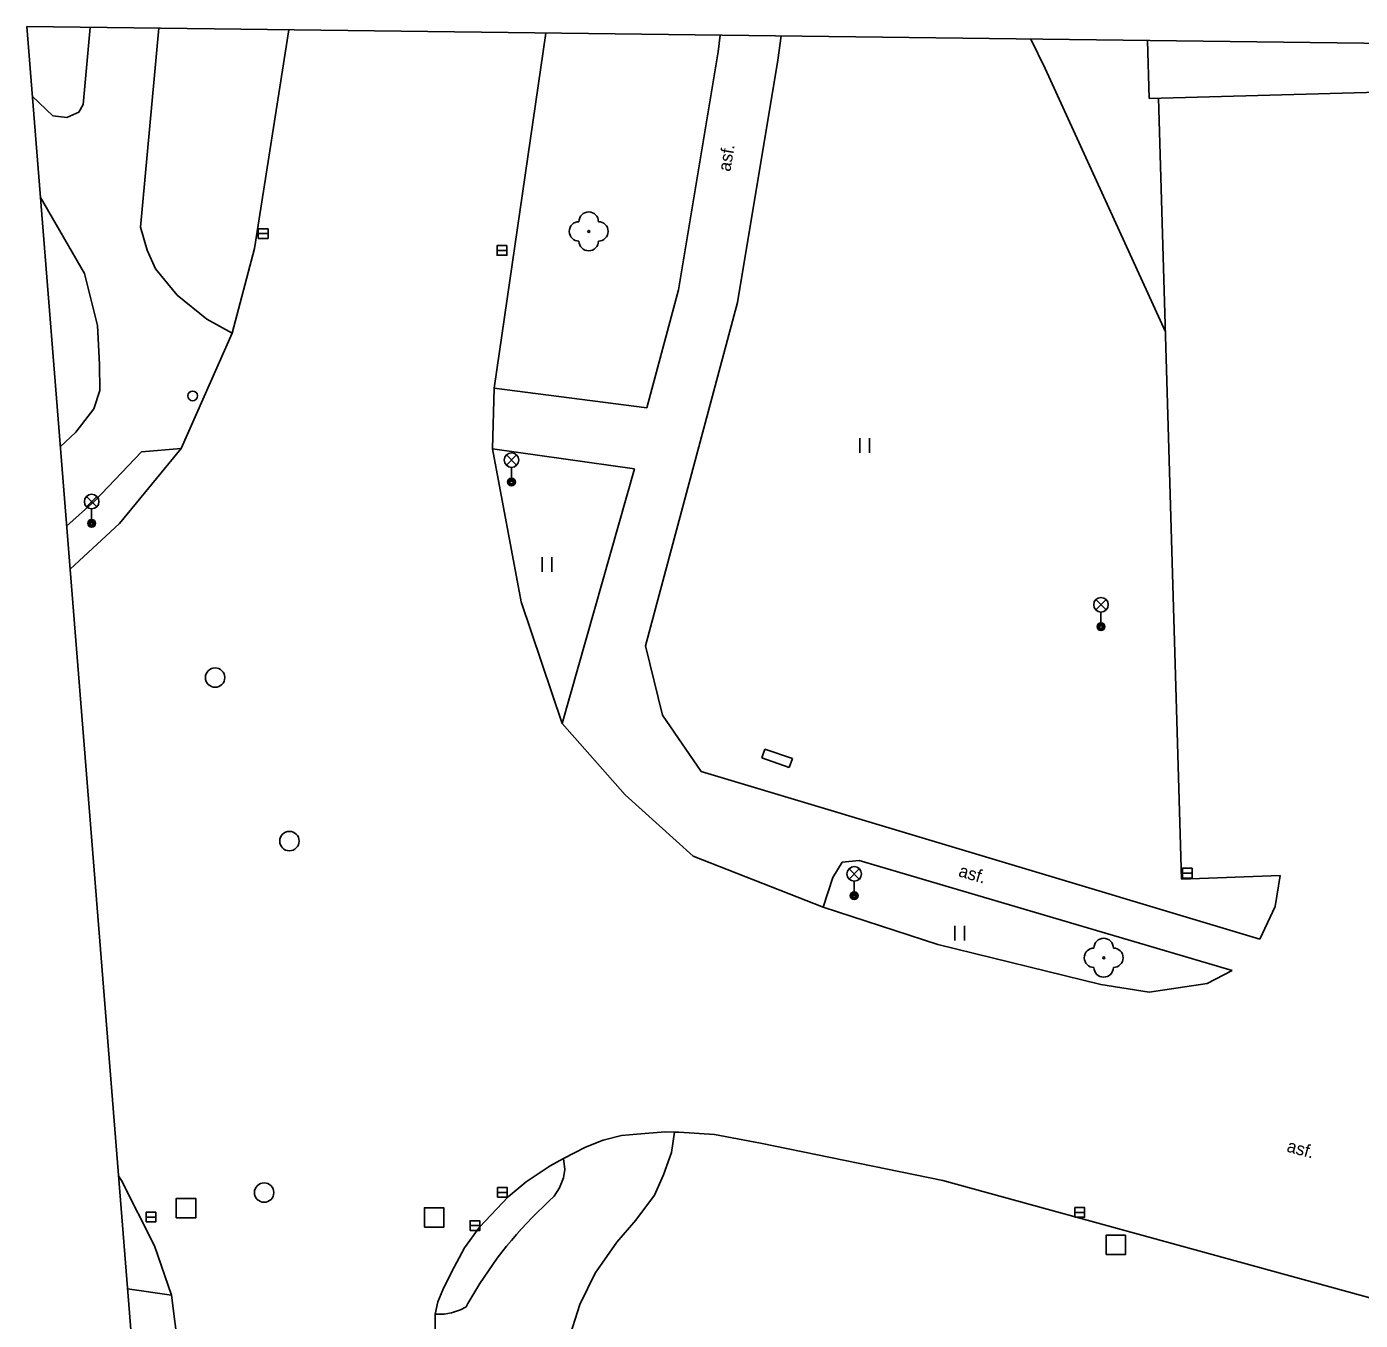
# Model space of a CAD drawing. Extents: x -641829 to -641525, y -1114855 to -1114359.
# Drawn here: x -641828.7 to -641760.1, y -1114425.4 to -1114358.9 of the extents above; entities that cross this region are included whole.
import ezdxf

# ---------------------------------------------------------------- set-up
doc = ezdxf.new("R2010")
doc.units = 0
for name, color, linetype in [('Vrstva 1', 7, 'Continuous'), ('Vrstva 10', 7, 'Continuous'), ('Vrstva 11', 7, 'Continuous'), ('Vrstva 14', 7, 'Continuous'), ('Vrstva 22', 7, 'Continuous'), ('Vrstva 26', 7, 'Continuous'), ('Vrstva 27', 7, 'Continuous'), ('Vrstva 28', 7, 'Continuous'), ('Vrstva 33', 7, 'Continuous'), ('Vrstva 36', 7, 'Continuous'), ('Vrstva 40', 7, 'Continuous'), ('Vrstva 5', 7, 'Continuous')]:
    doc.layers.add(name, color=color, linetype=linetype)

msp = doc.modelspace()

# ---------------------------------------------------------------- linework, layer by layer
at = {"layer": 'Vrstva 1'}
for p, q in [((-641525.3, -1114362.64), (-641828.67, -1114358.89)), ((-641828.67, -1114358.89), (-641812.64, -1114559.36))]:
    msp.add_line(p, q, dxfattribs=at)
at = {"layer": 'Vrstva 10'}
for p, q in [((-641815.193, -1114359.057), (-641816.95, -1114370.3)), ((-641801.975, -1114359.22), (-641804.63, -1114377.48)), ((-641769.29, -1114402.74), (-641770.48, -1114362.57)), ((-641816.95, -1114370.3), (-641818.1, -1114374.66)), ((-641818.1, -1114374.66), (-641820.73, -1114380.59)), ((-641804.63, -1114377.48), (-641804.72, -1114380.61)), ((-641820.73, -1114380.59), (-641823.9, -1114384.44)), ((-641804.72, -1114380.61), (-641803.25, -1114388.47)), ((-641823.9, -1114384.44), (-641826.439, -1114386.788)), ((-641803.25, -1114388.47), (-641801.13, -1114394.74)), ((-641801.13, -1114394.74), (-641797.9, -1114398.4)), ((-641797.9, -1114398.4), (-641794.4, -1114401.56)), ((-641787.71, -1114404.18), (-641794.4, -1114401.56)), ((-641764.22, -1114402.55), (-641769.29, -1114402.74)), ((-641764.47, -1114404.14), (-641764.22, -1114402.55)), ((-641787.71, -1114404.18), (-641781.82, -1114406.1)), ((-641765.26, -1114405.83), (-641764.47, -1114404.14)), ((-641781.82, -1114406.1), (-641773.44, -1114408.15)), ((-641767.97, -1114408.11), (-641766.69, -1114407.44)), ((-641773.44, -1114408.15), (-641770.95, -1114408.55)), ((-641770.95, -1114408.55), (-641767.97, -1114408.11)), ((-641799.02, -1114416.16), (-641798.08, -1114415.93)), ((-641798.08, -1114415.93), (-641797.3, -1114415.85)), ((-641797.3, -1114415.85), (-641795.84, -1114415.74)), ((-641795.84, -1114415.74), (-641795.36, -1114415.75)), ((-641795.36, -1114415.75), (-641795.13, -1114415.75)), ((-641793.31, -1114415.87), (-641795.13, -1114415.75)), ((-641790.93, -1114416.31), (-641793.31, -1114415.87)), ((-641801.06, -1114417.11), (-641799.93, -1114416.53)), ((-641799.93, -1114416.53), (-641799.02, -1114416.16)), ((-641790.93, -1114416.31), (-641781.57, -1114418.24)), ((-641801.75, -1114417.48), (-641801.06, -1114417.11)), ((-641823.943, -1114418.005), (-641823.8, -1114418.23)), ((-641802.99, -1114418.31), (-641801.75, -1114417.48)), ((-641823.8, -1114418.23), (-641822.1, -1114421.59)), ((-641803.91, -1114419.07), (-641802.99, -1114418.31)), ((-641781.57, -1114418.24), (-641753.07, -1114426.08)), ((-641805.38, -1114420.63), (-641803.91, -1114419.07)), ((-641806.16, -1114421.7), (-641805.38, -1114420.63)), ((-641822.1, -1114421.59), (-641821.23, -1114424.14)), ((-641806.82, -1114422.96), (-641806.16, -1114421.7)), ((-641807.27, -1114423.86), (-641806.82, -1114422.96)), ((-641821.23, -1114424.14), (-641820.82, -1114427.32)), ((-641807.27, -1114423.86), (-641807.52, -1114424.48)), ((-641807.52, -1114424.48), (-641807.67, -1114425.11)), ((-641807.68, -1114427.59), (-641807.67, -1114425.11))]:
    msp.add_line(p, q, dxfattribs=at)
at = {"layer": 'Vrstva 11'}
for p, q in [((-641825.77, -1114362.9), (-641825.406, -1114358.93)), ((-641822.82, -1114369.21), (-641821.866, -1114358.974)), ((-641793.11, -1114360.18), (-641793.003, -1114359.331)), ((-641790.04, -1114360.62), (-641789.882, -1114359.369)), ((-641795.15, -1114372.42), (-641793.11, -1114360.18)), ((-641792.12, -1114373.08), (-641790.04, -1114360.62)), ((-641828.384, -1114362.462), (-641827.32, -1114363.47)), ((-641825.77, -1114362.9), (-641825.99, -1114363.28)), ((-641826.61, -1114363.57), (-641827.32, -1114363.47)), ((-641825.99, -1114363.28), (-641826.61, -1114363.57)), ((-641827.97, -1114367.644), (-641825.69, -1114371.58)), ((-641822.48, -1114370.39), (-641822.82, -1114369.21)), ((-641822.05, -1114371.35), (-641822.48, -1114370.39)), ((-641820.94, -1114372.7), (-641822.05, -1114371.35)), ((-641825.02, -1114374.26), (-641825.69, -1114371.58)), ((-641819.4, -1114373.93), (-641820.94, -1114372.7)), ((-641796.78, -1114378.49), (-641795.15, -1114372.42)), ((-641796.85, -1114390.73), (-641792.12, -1114373.08)), ((-641818.1, -1114374.66), (-641819.4, -1114373.93)), ((-641824.92, -1114376.26), (-641825.02, -1114374.26)), ((-641824.9, -1114377.61), (-641824.92, -1114376.26)), ((-641796.78, -1114378.49), (-641804.63, -1114377.48)), ((-641825.21, -1114378.55), (-641824.9, -1114377.61)), ((-641825.21, -1114378.55), (-641826.15, -1114379.75)), ((-641826.15, -1114379.75), (-641826.942, -1114380.503)), ((-641822.76, -1114380.75), (-641825.16, -1114383.28)), ((-641822.76, -1114380.75), (-641820.73, -1114380.59)), ((-641797.42, -1114381.63), (-641804.72, -1114380.61)), ((-641801.13, -1114394.74), (-641797.42, -1114381.63)), ((-641825.16, -1114383.28), (-641826.616, -1114384.574)), ((-641795.98, -1114394.3), (-641796.85, -1114390.73)), ((-641793.99, -1114397.2), (-641795.98, -1114394.3)), ((-641790.71, -1114396.05), (-641790.87, -1114396.49)), ((-641789.3, -1114396.54), (-641790.71, -1114396.05)), ((-641790.87, -1114396.49), (-641789.46, -1114397)), ((-641789.3, -1114396.54), (-641789.46, -1114397)), ((-641765.26, -1114405.83), (-641793.99, -1114397.2)), ((-641786.73, -1114401.86), (-641787.22, -1114402.65)), ((-641785.86, -1114401.77), (-641786.73, -1114401.86)), ((-641766.69, -1114407.44), (-641785.86, -1114401.77)), ((-641787.71, -1114404.18), (-641787.22, -1114402.65)), ((-641795.36, -1114415.75), (-641795.52, -1114416.8)), ((-641801, -1114417.67), (-641801.06, -1114417.11)), ((-641795.52, -1114416.8), (-641795.93, -1114417.95)), ((-641801.07, -1114418.1), (-641801, -1114417.67)), ((-641795.93, -1114417.95), (-641796.38, -1114418.99)), ((-641801.54, -1114419.05), (-641801.27, -1114418.62)), ((-641801.27, -1114418.62), (-641801.07, -1114418.1)), ((-641802.12, -1114419.59), (-641801.83, -1114419.32)), ((-641801.83, -1114419.32), (-641801.54, -1114419.05)), ((-641796.38, -1114418.99), (-641797.34, -1114420.28)), ((-641802.68, -1114420.14), (-641802.4, -1114419.86)), ((-641802.4, -1114419.86), (-641802.12, -1114419.59)), ((-641803.48, -1114421.01), (-641803.22, -1114420.72)), ((-641803.22, -1114420.72), (-641802.95, -1114420.43)), ((-641802.95, -1114420.43), (-641802.68, -1114420.14)), ((-641797.34, -1114420.28), (-641798.32, -1114421.41)), ((-641803.99, -1114421.62), (-641803.74, -1114421.32)), ((-641803.74, -1114421.32), (-641803.48, -1114421.01)), ((-641798.32, -1114421.41), (-641799.44, -1114423)), ((-641804.47, -1114422.24), (-641804.23, -1114421.93)), ((-641804.23, -1114421.93), (-641803.99, -1114421.62)), ((-641804.93, -1114422.89), (-641804.7, -1114422.56)), ((-641804.7, -1114422.56), (-641804.47, -1114422.24)), ((-641805.58, -1114423.88), (-641805.37, -1114423.54)), ((-641805.37, -1114423.54), (-641805.15, -1114423.21)), ((-641805.15, -1114423.21), (-641804.93, -1114422.89)), ((-641799.44, -1114423), (-641800.22, -1114424.61)), ((-641823.478, -1114423.816), (-641821.23, -1114424.14)), ((-641805.98, -1114424.56), (-641805.78, -1114424.22)), ((-641805.78, -1114424.22), (-641805.58, -1114423.88)), ((-641806.36, -1114424.89), (-641806.82, -1114425.04)), ((-641806.07, -1114424.73), (-641806.36, -1114424.89)), ((-641806.07, -1114424.73), (-641805.98, -1114424.56)), ((-641800.22, -1114424.61), (-641800.95, -1114426.88)), ((-641807.2, -1114425.11), (-641807.67, -1114425.11)), ((-641806.82, -1114425.04), (-641807.2, -1114425.11))]:
    msp.add_line(p, q, dxfattribs=at)
at = {"layer": 'Vrstva 14'}
for p, q in [((-641777.038, -1114359.528), (-641776.3, -1114361.05)), ((-641776.3, -1114361.05), (-641770.12, -1114374.59))]:
    msp.add_line(p, q, dxfattribs=at)
at = {"layer": 'Vrstva 22'}
for centre in [(-641799.77, -1114369.42), (-641773.29, -1114406.78)]:
    msp.add_circle(centre, 0.05, dxfattribs=at)
for centre, start, end in [((-641799.77, -1114368.92), 0, 180), ((-641800.27, -1114369.42), 90, 270), ((-641799.27, -1114369.42), 270, 90), ((-641799.77, -1114369.92), 180, 0), ((-641773.79, -1114406.78), 90, 270), ((-641773.29, -1114406.28), 0, 180), ((-641772.79, -1114406.78), 270, 90), ((-641773.29, -1114407.28), 180, 0)]:
    msp.add_arc(centre, 0.5, start, end, dxfattribs=at)
at = {"layer": 'Vrstva 26'}
for points in [[(-641820.98, -1114420.16), (-641819.98, -1114420.16), (-641819.98, -1114419.16), (-641820.98, -1114419.16)], [(-641808.22, -1114420.64), (-641807.22, -1114420.64), (-641807.22, -1114419.64), (-641808.22, -1114419.64)], [(-641773.17, -1114422.05), (-641772.17, -1114422.05), (-641772.17, -1114421.05), (-641773.17, -1114421.05)]]:
    msp.add_lwpolyline(points, close=True, dxfattribs=at)
at = {"layer": 'Vrstva 27'}
for p, q in [((-641816.26, -1114369.53), (-641816.76, -1114369.53)), ((-641803.98, -1114370.4), (-641804.48, -1114370.4)), ((-641768.74, -1114402.43), (-641769.24, -1114402.43)), ((-641804.46, -1114418.85), (-641803.96, -1114418.85)), ((-641774.77, -1114419.88), (-641774.27, -1114419.88)), ((-641822.53, -1114420.12), (-641822.03, -1114420.12)), ((-641805.87, -1114420.56), (-641805.37, -1114420.56))]:
    msp.add_line(p, q, dxfattribs=at)
for points in [[(-641816.26, -1114369.28), (-641816.76, -1114369.28), (-641816.76, -1114369.78), (-641816.26, -1114369.78)], [(-641803.98, -1114370.15), (-641804.48, -1114370.15), (-641804.48, -1114370.65), (-641803.98, -1114370.65)], [(-641768.74, -1114402.18), (-641769.24, -1114402.18), (-641769.24, -1114402.68), (-641768.74, -1114402.68)], [(-641804.46, -1114419.1), (-641803.96, -1114419.1), (-641803.96, -1114418.6), (-641804.46, -1114418.6)], [(-641822.53, -1114420.37), (-641822.03, -1114420.37), (-641822.03, -1114419.87), (-641822.53, -1114419.87)], [(-641774.77, -1114420.13), (-641774.27, -1114420.13), (-641774.27, -1114419.63), (-641774.77, -1114419.63)], [(-641805.87, -1114420.81), (-641805.37, -1114420.81), (-641805.37, -1114420.31), (-641805.87, -1114420.31)]]:
    msp.add_lwpolyline(points, close=True, dxfattribs=at)
for centre in [(-641818.98, -1114392.37), (-641815.16, -1114400.78), (-641816.46, -1114418.86)]:
    msp.add_circle(centre, 0.5, dxfattribs=at)
at = {"layer": 'Vrstva 28'}
msp.add_circle((-641820.13, -1114377.88), 0.25, dxfattribs=at)
at = {"layer": 'Vrstva 33'}
for p, q in [((-641804.004, -1114381.45), (-641803.476, -1114380.92)), ((-641804.004, -1114380.92), (-641803.476, -1114381.45)), ((-641803.74, -1114381.56), (-641803.74, -1114382.31)), ((-641825.594, -1114383.58), (-641825.066, -1114383.05)), ((-641825.594, -1114383.05), (-641825.066, -1114383.58)), ((-641825.33, -1114383.69), (-641825.33, -1114384.44)), ((-641773.694, -1114388.89), (-641773.166, -1114388.36)), ((-641773.694, -1114388.36), (-641773.166, -1114388.89)), ((-641773.43, -1114389), (-641773.43, -1114389.75)), ((-641786.384, -1114402.73), (-641785.856, -1114402.2)), ((-641786.384, -1114402.2), (-641785.856, -1114402.73)), ((-641786.12, -1114402.84), (-641786.12, -1114403.59))]:
    msp.add_line(p, q, dxfattribs=at)
for centre, radius in [((-641803.74, -1114381.185), 0.375), ((-641803.74, -1114382.31), 0.2), ((-641803.74, -1114382.31), 0.145), ((-641803.74, -1114382.31), 0.0876), ((-641825.33, -1114383.315), 0.375), ((-641825.33, -1114384.44), 0.2), ((-641825.33, -1114384.44), 0.145), ((-641825.33, -1114384.44), 0.0876), ((-641773.43, -1114388.625), 0.375), ((-641773.43, -1114389.75), 0.2), ((-641773.43, -1114389.75), 0.145), ((-641773.43, -1114389.75), 0.0876), ((-641786.12, -1114402.465), 0.375), ((-641786.12, -1114403.59), 0.2), ((-641786.12, -1114403.59), 0.145), ((-641786.12, -1114403.59), 0.0876)]:
    msp.add_circle(centre, radius, dxfattribs=at)
at = {"layer": 'Vrstva 36'}
for p, q in [((-641785.834, -1114380.812), (-641785.834, -1114380.064)), ((-641785.334, -1114380.812), (-641785.334, -1114380.064)), ((-641802.164, -1114386.934), (-641802.164, -1114386.182)), ((-641801.664, -1114386.934), (-641801.664, -1114386.182)), ((-641780.944, -1114405.894), (-641780.944, -1114405.142)), ((-641780.444, -1114405.894), (-641780.444, -1114405.142))]:
    msp.add_line(p, q, dxfattribs=at)
at = {"layer": 'Vrstva 5'}
for p, q in [((-641771.042, -1114359.602), (-641770.96, -1114362.58)), ((-641770.96, -1114362.58), (-641741.54, -1114361.78))]:
    msp.add_line(p, q, dxfattribs=at)

# ---------------------------------------------------------------- texts
at = {"layer": 'Vrstva 40'}
for height, rotation, p in [(0.65, 80.52174, (-641792.49, -1114366.37)), (0.6499, 343.52312, (-641780.8, -1114402.58)), (0.65, 344.61978, (-641763.92, -1114416.74))]:
    msp.add_text('asf.', height=height, rotation=rotation, dxfattribs=at).set_placement(p)

doc.saveas('drawing.dxf')
